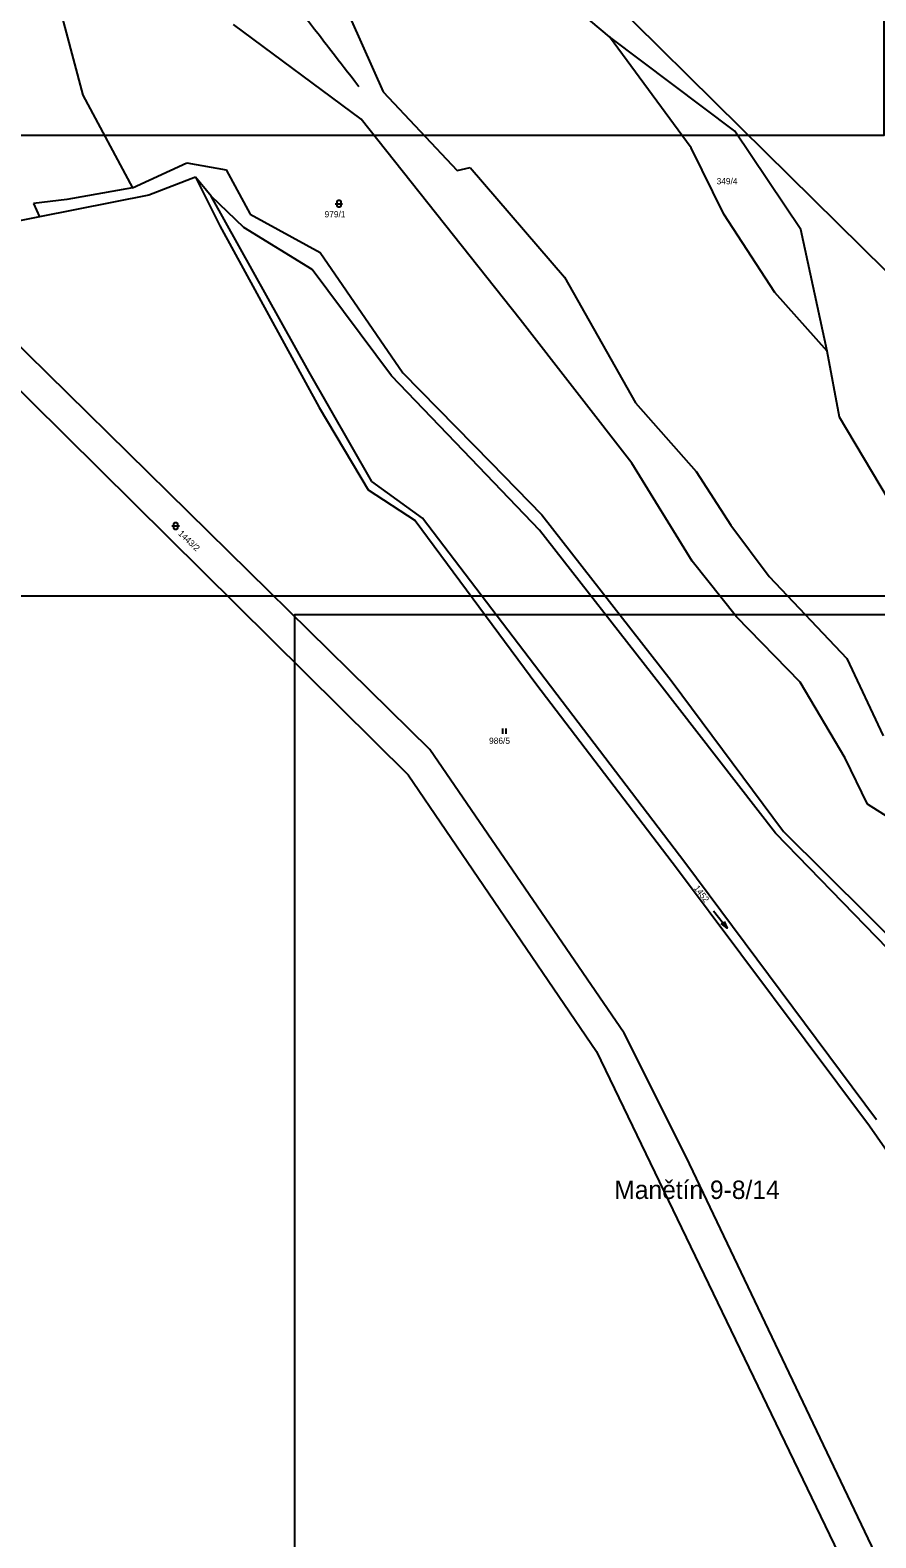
# Model space of a CAD drawing. Extents: x -852001 to -842497, y -1063614 to -1052182.
# Drawn here: x -848982.2 to -848752.2, y -1056881.4 to -1056471.5 of the extents above; entities that cross this region are included whole.
import ezdxf

# ---------------------------------------------------------------- set-up
doc = ezdxf.new("R2010")
doc.units = 0
for name, color, linetype in [('Default', 7, 'Continuous'), ('KLADY_ZMVM', 7, 'Continuous'), ('KN_HRANICE', 7, 'Continuous'), ('KN_KULTURY', 7, 'Continuous'), ('KN_PARCELY', 7, 'Continuous'), ('LEGENDA', 7, 'Continuous'), ('Železniční svršek', 7, 'Continuous')]:
    doc.layers.add(name, color=color, linetype=linetype)

# ---------------------------------------------------------------- blocks, each defined once
blk = doc.blocks.new('306')
at = {"layer": 'Default'}
for p, q in [((-0.5, 1.5), (-0.5, 0)), ((0.5, 0), (0.5, 1.5))]:
    blk.add_line(p, q, dxfattribs=at)
blk = doc.blocks.new('316')
at = {"layer": 'Default'}
for points in [[(-1, 1), (0.27, 1), (1, 1)], [(-0.5, 1.5), (-0.4, 1.79), (-0.15, 1.97), (0.16, 1.97), (0.41, 1.79), (0.51, 1.5), (0.51, 0.5), (0.41, 0.21), (0.16, 0.03), (-0.15, 0.03), (-0.4, 0.21), (-0.5, 0.5), (-0.5, 1.5)]]:
    blk.add_lwpolyline(points, dxfattribs=at)
blk = doc.blocks.new('802')
at = {"layer": 'Default'}
blk.add_line((-3, 0), (3, 0), dxfattribs=at)
blk.add_lwpolyline([(1, 0.5), (3, 0), (1, -0.5)], dxfattribs=at)

msp = doc.modelspace()

# ---------------------------------------------------------------- linework, layer by layer
at = {"layer": 'KLADY_ZMVM'}
msp.add_lwpolyline([(-849375, -1056500), (-848750, -1056500), (-848750, -1056000)], dxfattribs=at)
at = {"layer": 'KN_HRANICE'}
for p, q in [((-848788.89, -1056498.09), (-848844.87, -1056442.82)), ((-848788.89, -1056498.09), (-848844.87, -1056442.82)), ((-848977.76, -1056451.81), (-848967.94, -1056489.14)), ((-848977.76, -1056451.81), (-848967.94, -1056489.14)), ((-848898.41, -1056460.89), (-848886.21, -1056488.24)), ((-848898.41, -1056460.89), (-848886.21, -1056488.24)), ((-848824.7, -1056473.29), (-848832.57, -1056466.67)), ((-848824.7, -1056473.29), (-848832.57, -1056466.67)), ((-848892.25, -1056495.68), (-848926.93, -1056469.99)), ((-848892.25, -1056495.68), (-848926.93, -1056469.99)), ((-848802.49, -1056503.46), (-848824.7, -1056473.29)), ((-848790.56, -1056498.99), (-848824.7, -1056473.29)), ((-848802.49, -1056503.46), (-848824.7, -1056473.29)), ((-848790.56, -1056498.99), (-848824.7, -1056473.29)), ((-848967.94, -1056489.14), (-848954.44, -1056514.31)), ((-848967.94, -1056489.14), (-848954.44, -1056514.31)), ((-848886.21, -1056488.24), (-848866.08, -1056509.67)), ((-848886.21, -1056488.24), (-848866.08, -1056509.67)), ((-848849.01, -1056550.16), (-848892.25, -1056495.68)), ((-848849.01, -1056550.16), (-848892.25, -1056495.68)), ((-848772.63, -1056525.66), (-848790.56, -1056498.99)), ((-848772.63, -1056525.66), (-848790.56, -1056498.99)), ((-848724.3, -1056561.87), (-848788.89, -1056498.09)), ((-848724.3, -1056561.87), (-848788.89, -1056498.09)), ((-848793.61, -1056521.55), (-848802.49, -1056503.46)), ((-848793.61, -1056521.55), (-848802.49, -1056503.46)), ((-848954.44, -1056514.31), (-848939.6, -1056507.59)), ((-848954.44, -1056514.31), (-848939.6, -1056507.59)), ((-848939.6, -1056507.59), (-848928.93, -1056509.43)), ((-848939.6, -1056507.59), (-848928.93, -1056509.43)), ((-848928.93, -1056509.43), (-848922.36, -1056521.52)), ((-848928.93, -1056509.43), (-848922.36, -1056521.52)), ((-848866.08, -1056509.67), (-848862.59, -1056508.83)), ((-848866.08, -1056509.67), (-848862.59, -1056508.83)), ((-848862.59, -1056508.83), (-848836.91, -1056538.6)), ((-848862.59, -1056508.83), (-848836.91, -1056538.6)), ((-848937.27, -1056511.41), (-848949.92, -1056516.36)), ((-848937.27, -1056511.41), (-848949.92, -1056516.36)), ((-848933.03, -1056516.64), (-848937.27, -1056511.41)), ((-848937.27, -1056511.41), (-848930.66, -1056524.65)), ((-848933.03, -1056516.64), (-848937.27, -1056511.41)), ((-848937.27, -1056511.41), (-848930.66, -1056524.65)), ((-848972.25, -1056517.56), (-848981.3, -1056518.62)), ((-848972.25, -1056517.56), (-848981.3, -1056518.62)), ((-848949.92, -1056516.36), (-848979.67, -1056522.23)), ((-848949.92, -1056516.36), (-848979.67, -1056522.23)), ((-848954.44, -1056514.31), (-848972.25, -1056517.56)), ((-848954.44, -1056514.31), (-848972.25, -1056517.56)), ((-848924.12, -1056525.13), (-848933.03, -1056516.64)), ((-848906.49, -1056564.25), (-848933.03, -1056516.64)), ((-848924.12, -1056525.13), (-848933.03, -1056516.64)), ((-848906.49, -1056564.25), (-848933.03, -1056516.64)), ((-848981.3, -1056518.62), (-848979.67, -1056522.23)), ((-848981.3, -1056518.62), (-848979.67, -1056522.23)), ((-848922.36, -1056521.52), (-848903.38, -1056531.94)), ((-848922.36, -1056521.52), (-848903.38, -1056531.94)), ((-848779.71, -1056542.8), (-848793.61, -1056521.55)), ((-848779.71, -1056542.8), (-848793.61, -1056521.55)), ((-848979.67, -1056522.23), (-848985.11, -1056523.29)), ((-848979.67, -1056522.23), (-848985.11, -1056523.29)), ((-848930.66, -1056524.65), (-848903.6, -1056574.08)), ((-848930.66, -1056524.65), (-848903.6, -1056574.08)), ((-848905.5, -1056536.53), (-848924.12, -1056525.13)), ((-848905.5, -1056536.53), (-848924.12, -1056525.13)), ((-848765.48, -1056558.74), (-848772.63, -1056525.66)), ((-848765.48, -1056558.74), (-848772.63, -1056525.66)), ((-848903.38, -1056531.94), (-848880.84, -1056564.67)), ((-848903.38, -1056531.94), (-848880.84, -1056564.67)), ((-848883.95, -1056565.45), (-848905.5, -1056536.53)), ((-848883.95, -1056565.45), (-848905.5, -1056536.53)), ((-848836.91, -1056538.6), (-848817.62, -1056572.77)), ((-848836.91, -1056538.6), (-848817.62, -1056572.77)), ((-848765.48, -1056558.74), (-848779.71, -1056542.8)), ((-848765.48, -1056558.74), (-848779.71, -1056542.8)), ((-848818.64, -1056589.2), (-848849.01, -1056550.16)), ((-848818.64, -1056589.2), (-848849.01, -1056550.16)), ((-849001.42, -1056553.28), (-848879.42, -1056673.93)), ((-849001.42, -1056553.28), (-848879.42, -1056673.93)), ((-848873.55, -1056667.07), (-848988.42, -1056554.12)), ((-848873.55, -1056667.07), (-848988.42, -1056554.12)), ((-848762.14, -1056576.71), (-848765.48, -1056558.74)), ((-848762.14, -1056576.71), (-848765.48, -1056558.74)), ((-848889.32, -1056594.23), (-848906.49, -1056564.25)), ((-848889.32, -1056594.23), (-848906.49, -1056564.25)), ((-848864.37, -1056585.81), (-848883.95, -1056565.45)), ((-848864.37, -1056585.81), (-848883.95, -1056565.45)), ((-848880.84, -1056564.67), (-848856.95, -1056589.06)), ((-848880.84, -1056564.67), (-848856.95, -1056589.06)), ((-848903.6, -1056574.08), (-848890.31, -1056596.42)), ((-848903.6, -1056574.08), (-848890.31, -1056596.42)), ((-848817.62, -1056572.77), (-848801.1, -1056591.44)), ((-848817.62, -1056572.77), (-848801.1, -1056591.44)), ((-848748.78, -1056599.06), (-848762.14, -1056576.71)), ((-848748.78, -1056599.06), (-848762.14, -1056576.71)), ((-848843.74, -1056607.38), (-848864.37, -1056585.81)), ((-848843.74, -1056607.38), (-848864.37, -1056585.81)), ((-848856.95, -1056589.06), (-848843.1, -1056603.21)), ((-848856.95, -1056589.06), (-848843.1, -1056603.21)), ((-848802.15, -1056615.81), (-848818.64, -1056589.2)), ((-848802.15, -1056615.81), (-848818.64, -1056589.2)), ((-848801.1, -1056591.44), (-848791.72, -1056606.09)), ((-848801.1, -1056591.44), (-848791.72, -1056606.09)), ((-848875.54, -1056604.12), (-848889.32, -1056594.23)), ((-848875.54, -1056604.12), (-848889.32, -1056594.23)), ((-848890.31, -1056596.42), (-848877.52, -1056604.83)), ((-848890.31, -1056596.42), (-848877.52, -1056604.83)), ((-848804.16, -1056697.81), (-848875.54, -1056604.12)), ((-848804.16, -1056697.81), (-848875.54, -1056604.12)), ((-848843.1, -1056603.21), (-848807.91, -1056648.31)), ((-848843.1, -1056603.21), (-848807.91, -1056648.31)), ((-848877.52, -1056604.83), (-848844.48, -1056649.45)), ((-848877.52, -1056604.83), (-848844.48, -1056649.45)), ((-848810.95, -1056649.3), (-848843.74, -1056607.38)), ((-848810.95, -1056649.3), (-848843.74, -1056607.38)), ((-848791.72, -1056606.09), (-848781.23, -1056620.06)), ((-848791.72, -1056606.09), (-848781.23, -1056620.06)), ((-848790.18, -1056631.03), (-848802.15, -1056615.81)), ((-848790.18, -1056631.03), (-848802.15, -1056615.81)), ((-848781.23, -1056620.06), (-848760.1, -1056642.31)), ((-848781.23, -1056620.06), (-848760.1, -1056642.31)), ((-848772.81, -1056648.73), (-848790.18, -1056631.03)), ((-848772.81, -1056648.73), (-848790.18, -1056631.03)), ((-848760.1, -1056642.31), (-848750.28, -1056663.37)), ((-848760.1, -1056642.31), (-848750.28, -1056663.37)), ((-848807.91, -1056648.31), (-848777.38, -1056689.39)), ((-848807.91, -1056648.31), (-848777.38, -1056689.39)), ((-848760.59, -1056669.41), (-848772.81, -1056648.73)), ((-848760.59, -1056669.41), (-848772.81, -1056648.73)), ((-848844.48, -1056649.45), (-848806.49, -1056699.22)), ((-848844.48, -1056649.45), (-848806.49, -1056699.22)), ((-848779.5, -1056689.82), (-848810.95, -1056649.3)), ((-848779.5, -1056689.82), (-848810.95, -1056649.3)), ((-848820.69, -1056744.21), (-848873.55, -1056667.07)), ((-848820.69, -1056744.21), (-848873.55, -1056667.07)), ((-848754.47, -1056681.92), (-848760.59, -1056669.41)), ((-848754.47, -1056681.92), (-848760.59, -1056669.41)), ((-848879.42, -1056673.93), (-848828.18, -1056749.16)), ((-848879.42, -1056673.93), (-848828.18, -1056749.16)), ((-848729.55, -1056697.85), (-848754.47, -1056681.92)), ((-848729.55, -1056697.85), (-848754.47, -1056681.92)), ((-848715.09, -1056756.28), (-848779.5, -1056689.82)), ((-848715.09, -1056756.28), (-848779.5, -1056689.82)), ((-848777.38, -1056689.39), (-848711.53, -1056754.66)), ((-848777.38, -1056689.39), (-848711.53, -1056754.66)), ((-848752.07, -1056767.76), (-848804.16, -1056697.81)), ((-848752.07, -1056767.76), (-848804.16, -1056697.81)), ((-848806.49, -1056699.22), (-848753.98, -1056769.38)), ((-848806.49, -1056699.22), (-848753.98, -1056769.38)), ((-848803.86, -1056777.8), (-848820.69, -1056744.21)), ((-848803.86, -1056777.8), (-848820.69, -1056744.21)), ((-848828.18, -1056749.16), (-848759.71, -1056891.14)), ((-848828.18, -1056749.16), (-848759.71, -1056891.14)), ((-848753.98, -1056769.38), (-848709.93, -1056832.61)), ((-848753.98, -1056769.38), (-848709.93, -1056832.61)), ((-848752.4, -1056885.52), (-848803.86, -1056777.8)), ((-848752.4, -1056885.52), (-848803.86, -1056777.8))]:
    msp.add_line(p, q, dxfattribs=at)
at = {"layer": 'LEGENDA'}
for points in [[(-849142.95, -1056625.24), (-848548.95, -1056625.24), (-848548.95, -1056205.24), (-849142.95, -1056205.24)], [(-848910.31, -1057050.45), (-848316.31, -1057050.45), (-848316.31, -1056630.45), (-848910.31, -1056630.45)]]:
    msp.add_lwpolyline(points, close=True, dxfattribs=at)
at = {"layer": 'Železniční svršek'}
msp.add_open_spline([(-848892.81, -1056486.91), (-848898.96, -1056478.95), (-848904.39, -1056471.91), (-848910.36, -1056464.18), (-848915.68, -1056457.29), (-848922.02, -1056449.05), (-848928.2, -1056441.01), (-848934.22, -1056433.18), (-848940.17, -1056425.45), (-848946.67, -1056417), (-848952.25, -1056409.77), (-848955.57, -1056405.45), (-848960.77, -1056398.71), (-848966.2, -1056391.67), (-848971.61, -1056384.64), (-848977.18, -1056377.42), (-848982.34, -1056370.71), (-848987.69, -1056363.77), (-848993.84, -1056355.79), (-848999.77, -1056348.09), (-849005.4, -1056340.62), (-849010.95, -1056332.79), (-849016.27, -1056324.7), (-849020.78, -1056317.03), (-849025.01, -1056309.08), (-849028.91, -1056301.1), (-849032.78, -1056292.63), (-849036.57, -1056284.16)], degree=3, dxfattribs=at)

# ---------------------------------------------------------------- block references
at = {"layer": 'KN_KULTURY'}
for name, p in [('316', (-848898.27, -1056519.68)), ('316', (-848898.27, -1056519.68)), ('316', (-848942.66, -1056607.27)), ('316', (-848942.66, -1056607.27)), ('306', (-848853.3, -1056662.82)), ('306', (-848853.3, -1056662.82))]:
    msp.add_blockref(name, p, dxfattribs=at)
at = {"layer": 'KN_KULTURY', "rotation": -52.32166400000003}
msp.add_blockref('802', (-848794.53, -1056713.29), dxfattribs=at)
msp.add_blockref('802', (-848794.53, -1056713.29), dxfattribs=at)

# ---------------------------------------------------------------- texts
at = {"layer": 'KLADY_ZMVM'}
msp.add_text('Manětín 9-8/14', height=5, dxfattribs=at).set_placement((-848823.37, -1056789.25))
at = {"layer": 'KN_PARCELY'}
for s, p in [('349/4', (-848795.54, -1056513.38)), ('349/4', (-848795.54, -1056513.38)), ('979/1', (-848902.16, -1056522.38)), ('979/1', (-848902.16, -1056522.38)), ('986/5', (-848857.43, -1056665.52)), ('986/5', (-848857.43, -1056665.52))]:
    msp.add_text(s, height=1.7, dxfattribs=at).set_placement(p)
for s, rotation, p in [('1443/2', 316.445, (-848942.11, -1056608.51)), ('1443/2', 316.445, (-848942.11, -1056608.51)), ('1452', 307.392, (-848801.84, -1056704.78)), ('1452', 307.392, (-848801.84, -1056704.78))]:
    msp.add_text(s, height=1.7, rotation=rotation, dxfattribs=at).set_placement(p)

doc.saveas('drawing.dxf')
